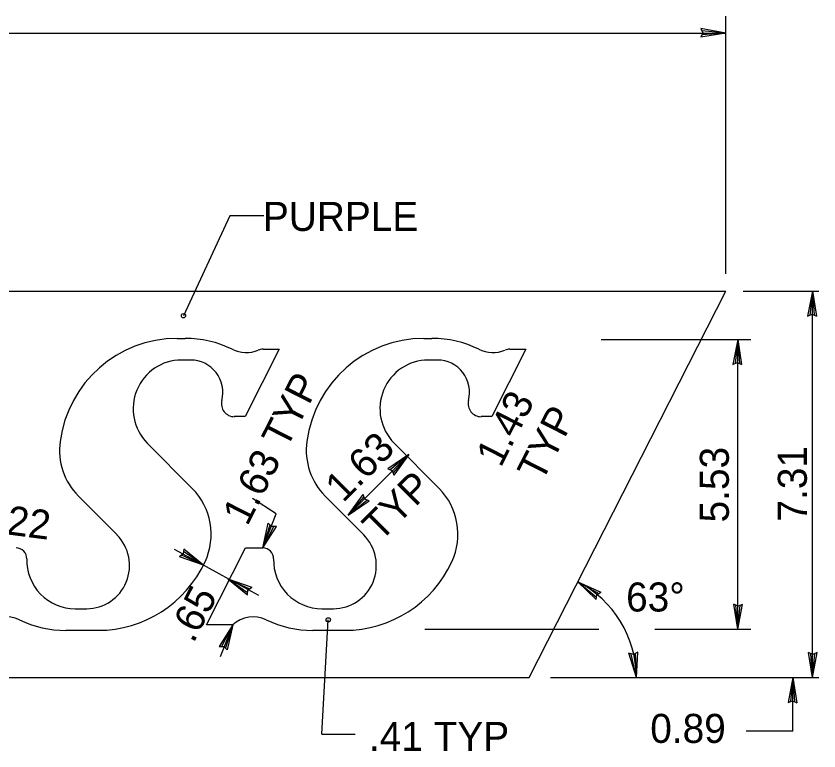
# Model space of a CAD drawing. Extents: x 10268197 to 10268826, y 2141503 to 2142677.
# Drawn here: x 10268809.85 to 10268826.28, y 2142362.75 to 2142377.79 of the extents above; entities that cross this region are included whole.
import ezdxf

# ---------------------------------------------------------------- set-up
doc = ezdxf.new("R2010")
doc.units = 0
for name, color, linetype in [('1', 7, 'Continuous'), ('21', 7, 'Continuous'), ('Default', 7, 'Continuous')]:
    doc.layers.add(name, color=color, linetype=linetype)

msp = doc.modelspace()

# ---------------------------------------------------------------- linework, layer by layer
at = {"layer": '1'}
for p, q in [((10268824.378, 2142372.509), (10268824.378, 2142377.787)), ((10268824.378, 2142377.436), (10268823.867, 2142377.535)), ((10268823.867, 2142377.535), (10268823.905, 2142377.444)), ((10268805.311, 2142377.436), (10268824.378, 2142377.436)), ((10268823.905, 2142377.444), (10268823.864, 2142377.354)), ((10268824.378, 2142377.436), (10268823.864, 2142377.354)), ((10268824.378, 2142377.436), (10268823.886, 2142377.401)), ((10268824.378, 2142377.436), (10268823.887, 2142377.487)), ((10268814.22, 2142373.697), (10268813.273, 2142371.654)), ((10268814.918, 2142373.697), (10268814.22, 2142373.697)), ((10268824.729, 2142372.157), (10268826.284, 2142372.157)), ((10268826.151, 2142372.157), (10268826.052, 2142371.646)), ((10268826.151, 2142372.157), (10268826.1, 2142371.666)), ((10268826.151, 2142364.248), (10268826.151, 2142372.157)), ((10268826.151, 2142372.157), (10268826.232, 2142371.643)), ((10268826.151, 2142372.157), (10268826.185, 2142371.665)), ((10268826.052, 2142371.646), (10268826.143, 2142371.684)), ((10268826.143, 2142371.684), (10268826.232, 2142371.643)), ((10268821.828, 2142371.169), (10268824.886, 2142371.169)), ((10268824.62, 2142371.169), (10268824.521, 2142370.658)), ((10268824.62, 2142371.169), (10268824.568, 2142370.678)), ((10268824.62, 2142365.237), (10268824.62, 2142371.169)), ((10268824.62, 2142371.169), (10268824.701, 2142370.655)), ((10268824.62, 2142371.169), (10268824.654, 2142370.676)), ((10268824.521, 2142370.658), (10268824.611, 2142370.695)), ((10268824.611, 2142370.695), (10268824.701, 2142370.655)), ((10268816.644, 2142367.572), (10268817.887, 2142368.815)), ((10268817.887, 2142368.815), (10268817.456, 2142368.523)), ((10268817.887, 2142368.815), (10268817.503, 2142368.503)), ((10268817.887, 2142368.815), (10268817.563, 2142368.442)), ((10268817.887, 2142368.815), (10268817.581, 2142368.393)), ((10268817.456, 2142368.523), (10268817.547, 2142368.485)), ((10268817.547, 2142368.485), (10268817.581, 2142368.393)), ((10268816.644, 2142367.572), (10268816.95, 2142367.993)), ((10268816.984, 2142367.901), (10268816.95, 2142367.993)), ((10268815.172, 2142367.603), (10268814.683, 2142367.914)), ((10268816.644, 2142367.572), (10268816.968, 2142367.944)), ((10268816.644, 2142367.572), (10268817.028, 2142367.882)), ((10268816.644, 2142367.572), (10268817.076, 2142367.863)), ((10268817.076, 2142367.863), (10268816.984, 2142367.901)), ((10268814.898, 2142366.904), (10268815.172, 2142367.603)), ((10268814.898, 2142366.904), (10268815.009, 2142367.412)), ((10268814.898, 2142366.904), (10268815.045, 2142367.374)), ((10268814.898, 2142366.904), (10268815.176, 2142367.343)), ((10268814.898, 2142366.904), (10268815.124, 2142367.343)), ((10268815.077, 2142367.341), (10268815.009, 2142367.412)), ((10268815.176, 2142367.343), (10268815.077, 2142367.341)), ((10268813.681, 2142366.548), (10268813.087, 2142366.872)), ((10268814.067, 2142366.338), (10268813.681, 2142366.548)), ((10268814.819, 2142365.927), (10268814.067, 2142366.338)), ((10268821.345, 2142366.206), (10268821.821, 2142365.994)), ((10268821.345, 2142366.206), (10268821.72, 2142365.845)), ((10268821.345, 2142366.206), (10268821.729, 2142365.895)), ((10268821.345, 2142366.206), (10268821.777, 2142365.967)), ((10268821.72, 2142365.845), (10268821.738, 2142365.942)), ((10268821.738, 2142365.942), (10268821.821, 2142365.994)), ((10268824.62, 2142365.237), (10268824.538, 2142365.751)), ((10268824.628, 2142365.71), (10268824.538, 2142365.751)), ((10268824.62, 2142365.237), (10268824.585, 2142365.729)), ((10268824.62, 2142365.237), (10268824.718, 2142365.748)), ((10268824.62, 2142365.237), (10268824.671, 2142365.728)), ((10268824.718, 2142365.748), (10268824.628, 2142365.71)), ((10268816.103, 2142363.093), (10268816.238, 2142365.43)), ((10268814.281, 2142365.326), (10268814.002, 2142364.886)), ((10268814.281, 2142365.326), (10268814.024, 2142364.671)), ((10268814.281, 2142365.326), (10268814.053, 2142364.887)), ((10268814.281, 2142365.326), (10268814.133, 2142364.855)), ((10268814.281, 2142365.326), (10268814.169, 2142364.818)), ((10268818.215, 2142365.237), (10268821.777, 2142365.237)), ((10268822.925, 2142365.237), (10268824.886, 2142365.237)), ((10268814.002, 2142364.886), (10268814.1, 2142364.888)), ((10268814.1, 2142364.888), (10268814.169, 2142364.818)), ((10268822.545, 2142364.248), (10268822.393, 2142364.747)), ((10268822.487, 2142364.719), (10268822.393, 2142364.747)), ((10268822.545, 2142364.248), (10268822.442, 2142364.731)), ((10268822.573, 2142364.768), (10268822.487, 2142364.719)), ((10268822.545, 2142364.248), (10268822.528, 2142364.742)), ((10268822.545, 2142364.248), (10268822.573, 2142364.768)), ((10268826.151, 2142364.248), (10268826.069, 2142364.762)), ((10268826.159, 2142364.722), (10268826.069, 2142364.762)), ((10268826.151, 2142364.248), (10268826.116, 2142364.741)), ((10268826.151, 2142364.248), (10268826.25, 2142364.759)), ((10268826.151, 2142364.248), (10268826.202, 2142364.74)), ((10268826.25, 2142364.759), (10268826.159, 2142364.722)), ((10268820.787, 2142364.248), (10268826.284, 2142364.248)), ((10268825.75, 2142364.248), (10268825.651, 2142363.738)), ((10268825.75, 2142364.248), (10268825.699, 2142363.757)), ((10268825.75, 2142363.15), (10268825.75, 2142364.248)), ((10268825.75, 2142364.248), (10268825.832, 2142363.735)), ((10268825.75, 2142364.248), (10268825.785, 2142363.757)), ((10268825.651, 2142363.738), (10268825.742, 2142363.776)), ((10268825.742, 2142363.776), (10268825.832, 2142363.735)), ((10268816.103, 2142363.093), (10268816.786, 2142363.093)), ((10268825.75, 2142363.15), (10268824.795, 2142363.15))]:
    msp.add_line(p, q, dxfattribs=at)
for centre in [(10268813.273, 2142371.654), (10268816.238, 2142365.431)]:
    msp.add_circle(centre, 0.0439, dxfattribs=at)
msp.add_arc((10268820.348, 2142364.249), 2.197, 0, 63.0012, dxfattribs=at)
at = {"layer": '21'}
for p, q in [((10268813.279, 2142366.88), (10268813.269, 2142366.782)), ((10268813.681, 2142366.548), (10268813.279, 2142366.88)), ((10268813.269, 2142366.782), (10268813.19, 2142366.722)), ((10268813.681, 2142366.548), (10268813.19, 2142366.722)), ((10268813.681, 2142366.548), (10268813.232, 2142366.754)), ((10268813.681, 2142366.548), (10268813.274, 2142366.829)), ((10268814.179, 2142366.273), (10268814.67, 2142366.099)), ((10268814.179, 2142366.273), (10268814.581, 2142365.941)), ((10268814.179, 2142366.273), (10268814.586, 2142365.993)), ((10268814.179, 2142366.273), (10268814.628, 2142366.068)), ((10268814.581, 2142365.941), (10268814.591, 2142366.039)), ((10268814.591, 2142366.039), (10268814.67, 2142366.099))]:
    msp.add_line(p, q, dxfattribs=at)
at = {"layer": 'Default'}
for p, q in [((10268799.315, 2142372.157), (10268824.378, 2142372.157)), ((10268820.349, 2142364.248), (10268824.378, 2142372.157)), ((10268813.142, 2142371.19), (10268813.308, 2142371.19)), ((10268818.194, 2142371.19), (10268818.361, 2142371.19)), ((10268815.232, 2142370.969), (10268814.534, 2142369.589)), ((10268814.902, 2142370.969), (10268815.232, 2142370.969)), ((10268820.284, 2142370.969), (10268819.586, 2142369.589)), ((10268819.955, 2142370.969), (10268820.284, 2142370.969)), ((10268813.42, 2142370.748), (10268813.231, 2142370.748)), ((10268818.472, 2142370.748), (10268818.283, 2142370.748)), ((10268814.534, 2142369.589), (10268814.314, 2142369.589)), ((10268819.586, 2142369.589), (10268819.366, 2142369.589)), ((10268812.532, 2142369.048), (10268813.453, 2142368.12)), ((10268817.585, 2142369.048), (10268818.506, 2142368.12)), ((10268811.912, 2142367.169), (10268811.121, 2142367.965)), ((10268816.964, 2142367.169), (10268816.173, 2142367.965)), ((10268813.747, 2142365.326), (10268814.545, 2142366.904)), ((10268814.545, 2142366.904), (10268814.898, 2142366.904)), ((10268811.053, 2142365.658), (10268811.291, 2142365.658)), ((10268816.106, 2142365.658), (10268816.343, 2142365.658)), ((10268811.526, 2142365.215), (10268810.866, 2142365.215)), ((10268814.281, 2142365.326), (10268813.747, 2142365.326)), ((10268816.579, 2142365.215), (10268815.918, 2142365.215)), ((10268798.581, 2142364.248), (10268820.349, 2142364.248))]:
    msp.add_line(p, q, dxfattribs=at)
for centre, major_axis, start_param, end_param in [((10268813.141, 2142368.756), (0, 2.434), 0, 1.436562), ((10268813.308, 2142368.978), (0, 2.213), 5.830963, 6.283185), ((10268818.194, 2142368.756), (0, 2.434), 0, 1.436562), ((10268818.361, 2142368.978), (0, 2.213), 5.830963, 6.283185), ((10268814.556, 2142371.565), (0, 0.664), 2.68937, 3.526171), ((10268814.902, 2142370.704), (0, 0.266), 0, 0.384579), ((10268819.608, 2142371.565), (0, 0.664), 2.68937, 3.526171), ((10268819.955, 2142370.704), (0, 0.266), 0, 0.384579), ((10268813.231, 2142369.752), (0, -0.996), 3.141593, 5.497787), ((10268813.42, 2142370.084), (0, -0.664), 1.321066, 3.141593), ((10268818.284, 2142369.752), (0, -0.996), 3.141593, 5.497787), ((10268818.472, 2142370.084), (0, -0.664), 1.321066, 3.141593), ((10268814.314, 2142369.854), (0, -0.266), 4.462658, 6.283185), ((10268819.366, 2142369.854), (0, -0.266), 4.462658, 6.283185), ((10268812.053, 2142368.904), (0, 1.328), 1.436562, 2.356194), ((10268817.105, 2142368.904), (0, 1.328), 1.436562, 2.356194), ((10268812.521, 2142367.181), (0, -1.328), 1.133591, 2.356194), ((10268817.574, 2142367.181), (0, -1.328), 1.133591, 2.356194), ((10268811.29, 2142366.543), (0, -0.885), 0, 2.356194), ((10268816.343, 2142366.543), (0, -0.885), 0, 2.356194), ((10268809.845, 2142366.682), (0, 0.221), 4.689114, 6.283185), ((10268814.898, 2142366.682), (0, 0.221), 4.689114, 6.283185), ((10268811.053, 2142366.654), (0, 0.996), 1.547521, 3.141593), ((10268816.106, 2142366.654), (0, 0.996), 1.547521, 3.141593), ((10268811.526, 2142367.65), (0, -2.434), 0, 1.133591), ((10268816.579, 2142367.65), (0, -2.434), 0, 1.133591), ((10268809.649, 2142364.874), (0, -0.62), 2.69443, 3.895387), ((10268814.702, 2142364.874), (0, -0.62), 2.69443, 3.895387), ((10268810.865, 2142367.428), (0, -2.213), 5.836023, 6.283185), ((10268815.918, 2142367.428), (0, -2.213), 5.836023, 6.283185)]:
    msp.add_ellipse(centre, major_axis=major_axis, ratio=0.992614, start_param=start_param, end_param=end_param, dxfattribs=at)

# ---------------------------------------------------------------- texts
at = {"layer": '1'}
for s, p in [('PURPLE', (10268814.9, 2142373.389)), ('63°', (10268822.335, 2142365.601)), ('0.89', (10268822.83, 2142362.912)), ('.41 TYP', (10268817.07, 2142362.748))]:
    msp.add_text(s, height=0.5942, dxfattribs=at).set_placement(p)
for s, rotation, p in [('1.63 TYP', 62.9994, (10268814.579, 2142367.331)), ('1.43', 63, (10268819.769, 2142368.532)), ('TYP', 63, (10268820.614, 2142368.227)), ('1.63', 45, (10268816.54, 2142367.812)), ('5.53', 90, (10268824.439, 2142367.424)), ('7.31', 90, (10268826.036, 2142367.443)), ('TYP', 45, (10268817.302, 2142367.009)), ('1.22', 352.5994, (10268808.975, 2142367.268)), ('.65', 63, (10268813.477, 2142364.936))]:
    msp.add_text(s, height=0.5942, rotation=rotation, dxfattribs=at).set_placement(p)

doc.saveas('drawing.dxf')
